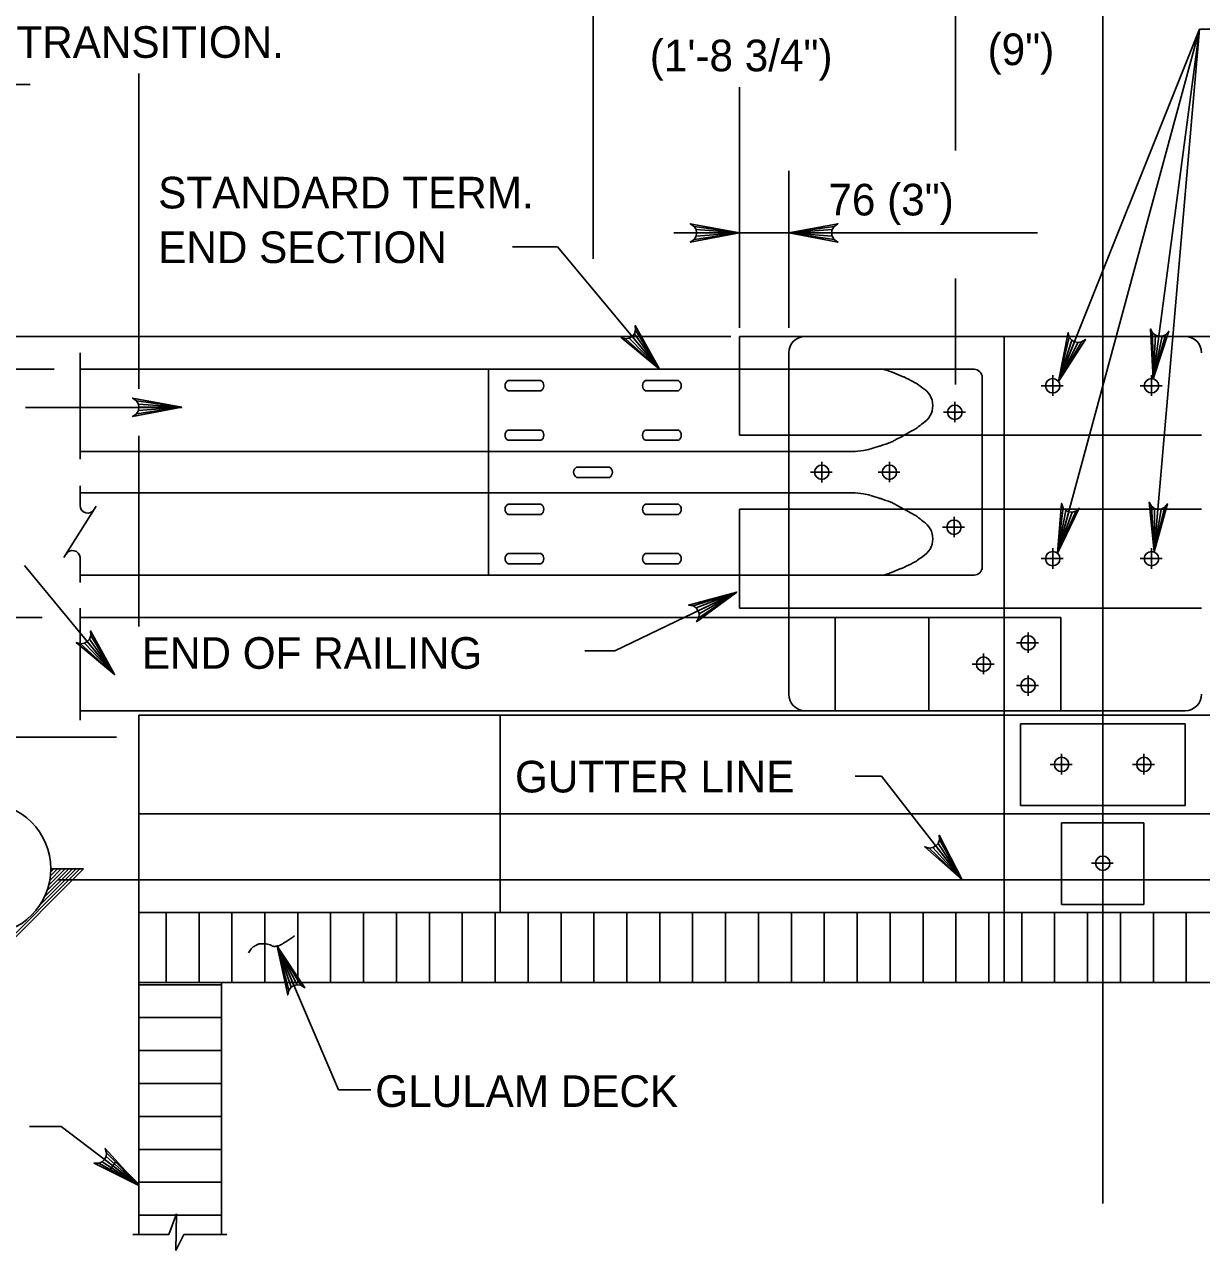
# Model space of a CAD drawing. Extents: x 0 to 36.3, y -66 to 0.
# Drawn here: x 4.419 to 8.89, y -16.519 to -11.865 of the extents above; entities that cross this region are included whole.
import ezdxf

# ---------------------------------------------------------------- set-up
doc = ezdxf.new("R2010")
doc.units = 0
for name, color, linetype in [('2', 7, 'Continuous'), ('3', 7, 'Continuous'), ('63', 7, 'Continuous')]:
    doc.layers.add(name, color=color, linetype=linetype)

# ---------------------------------------------------------------- blocks, each defined once
blk = doc.blocks.new('$X5430')
at = {"layer": '63'}
for p, q in [((5.4191, 3.4375), (5.6806, 3.4375)), ((5.4191, 3.3333), (5.6806, 3.3333)), ((5.4191, 3.2292), (5.6806, 3.2292)), ((5.4191, 3.125), (5.6806, 3.125)), ((5.4191, 3.0208), (5.6806, 3.0208)), ((5.4191, 2.9167), (5.6806, 2.9167)), ((5.4191, 2.8125), (5.6806, 2.8125)), ((5.4191, 2.7083), (5.6806, 2.7083))]:
    blk.add_line(p, q, dxfattribs=at)

msp = doc.modelspace()

# ---------------------------------------------------------------- linework, layer by layer
at = {"layer": '2'}
for p, q in [((7.1347, -13.0486), (9.1816, -13.0486)), ((8.1398, -13.0486), (8.1398, -15.5017)), ((4.6303, -13.1114), (4.6303, -13.5143)), ((7.3222, -13.1111), (7.3222, -13.9547)), ((4.6303, -13.1736), (6.1822, -13.1736)), ((6.1822, -13.1736), (6.1822, -13.9547)), ((6.1822, -13.1736), (8.0259, -13.1736)), ((6.2557, -13.2165), (6.3807, -13.2165)), ((6.7779, -13.2165), (6.9029, -13.2165)), ((7.1347, -13.1736), (7.1347, -13.4236)), ((8.0572, -13.2048), (8.0572, -13.9236)), ((8.3248, -13.1963), (8.3248, -13.2744)), ((8.6999, -13.1963), (8.6999, -13.2744)), ((6.2557, -13.2556), (6.3807, -13.2556)), ((6.7779, -13.2556), (6.9029, -13.2556)), ((8.2814, -13.2361), (8.3647, -13.2361)), ((8.6566, -13.2361), (8.7398, -13.2361)), ((7.953, -13.2968), (7.953, -13.3748)), ((7.9096, -13.3367), (7.9929, -13.3367)), ((6.2557, -13.404), (6.3807, -13.404)), ((6.2557, -13.4431), (6.3807, -13.4431)), ((6.7779, -13.404), (6.9029, -13.404)), ((6.7779, -13.4431), (6.9029, -13.4431)), ((7.1347, -13.4236), (8.8898, -13.4236)), ((4.6303, -13.4861), (7.5638, -13.4861)), ((7.4477, -13.5252), (7.4477, -13.6032)), ((7.7047, -13.5243), (7.7047, -13.6023)), ((6.5163, -13.5447), (6.6413, -13.5447)), ((6.5163, -13.5837), (6.6413, -13.5837)), ((7.4042, -13.5642), (7.4876, -13.5642)), ((7.6612, -13.5642), (7.7445, -13.5642)), ((4.6303, -13.6165), (4.6303, -13.6911)), ((4.6303, -13.6422), (7.5638, -13.6422)), ((4.6917, -13.6925), (4.5689, -13.8881)), ((6.2557, -13.6852), (6.3807, -13.6852)), ((6.2557, -13.7243), (6.3807, -13.7243)), ((6.7779, -13.6852), (6.9029, -13.6852)), ((6.7779, -13.7243), (6.9029, -13.7243)), ((7.1347, -13.7047), (8.8898, -13.7047)), ((7.1347, -13.7047), (7.1347, -13.9547)), ((7.9064, -13.7729), (7.9897, -13.7729)), ((7.9498, -13.7331), (7.9498, -13.8111)), ((8.3248, -13.8524), (8.3248, -13.9304)), ((8.6999, -13.8524), (8.6999, -13.9304)), ((4.6303, -13.8878), (4.6303, -13.9834)), ((6.2557, -13.8727), (6.3807, -13.8727)), ((6.2557, -13.9118), (6.3807, -13.9118)), ((6.7779, -13.8727), (6.9029, -13.8727)), ((6.7779, -13.9118), (6.9029, -13.9118)), ((8.2814, -13.8922), (8.3647, -13.8922)), ((8.6566, -13.8922), (8.7398, -13.8922)), ((4.6303, -13.9547), (8.0259, -13.9547)), ((7.3222, -13.9547), (7.3222, -14.4072)), ((7.1247, -14.0192), (6.6618, -14.2425)), ((4.6303, -14.0797), (4.6303, -14.506)), ((7.1347, -14.0797), (7.3222, -14.0797)), ((7.3222, -14.0797), (8.8898, -14.0797)), ((4.6303, -14.116), (8.3558, -14.116)), ((8.2311, -14.1723), (8.2311, -14.2503)), ((8.1877, -14.2122), (8.2709, -14.2122)), ((6.6618, -14.2425), (6.5474, -14.2425)), ((8.0619, -14.253), (8.0619, -14.331)), ((8.0185, -14.2928), (8.1018, -14.2928)), ((8.1877, -14.3736), (8.2709, -14.3736)), ((8.2311, -14.4134), (8.2311, -14.3354)), ((4.6303, -14.4697), (8.8273, -14.4697)), ((8.1398, -14.4697), (8.1398, -14.4861)), ((4.8531, -14.4861), (10.6802, -14.4861)), ((4.8531, -14.4861), (4.8531, -14.861)), ((6.2262, -14.4861), (6.2262, -15.236)), ((8.2023, -14.5197), (8.2023, -14.8297)), ((8.2023, -14.5197), (8.8273, -14.5197)), ((8.8273, -14.5197), (8.8273, -14.8297)), ((8.3586, -14.6337), (8.3586, -14.7117)), ((8.6711, -14.6337), (8.6711, -14.7117)), ((8.3152, -14.6735), (8.3985, -14.6735)), ((8.6277, -14.6735), (8.711, -14.6735)), ((8.2023, -14.8297), (8.8273, -14.8297)), ((4.8531, -14.861), (10.6802, -14.861)), ((8.3586, -14.8947), (8.3586, -15.2047)), ((8.3586, -14.8947), (8.6711, -14.8947)), ((8.6711, -14.8947), (8.6711, -15.2047)), ((8.5148, -15.0087), (8.5148, -15.0867)), ((8.4714, -15.0485), (8.5548, -15.0485)), ((8.3586, -15.2047), (8.6711, -15.2047)), ((4.8531, -15.236), (10.6802, -15.236)), ((4.8531, -15.5017), (10.6802, -15.5017)), ((4.8531, -15.5017), (4.8531, -16.4573)), ((5.1669, -15.5017), (5.1669, -16.4573)), ((4.5583, -16.0474), (4.4383, -16.0474)), ((4.8531, -16.2717), (4.5583, -16.0474))]:
    msp.add_line(p, q, dxfattribs=at)
msp.add_lwpolyline([(4.7667, -16.1808), (4.7436, -16.2135), (4.8531, -16.2665)], close=True, dxfattribs=at)
for centre in [(8.3248, -13.2361), (8.6999, -13.2361), (7.9529, -13.3367), (7.4476, -13.5642), (7.7046, -13.5642), (7.9498, -13.773), (8.3248, -13.8923), (8.6999, -13.8923), (8.231, -14.2122), (8.0619, -14.2929), (8.231, -14.3736), (8.3585, -14.6736), (8.671, -14.6736), (8.5148, -15.0486)]:
    msp.add_circle(centre, 0.0273, dxfattribs=at)
for centre, radius, start, end in [((7.3846, -13.1111), 0.0625, 90, 180), ((6.2674, -13.2361), 0.0228, 120.8559, 239.1441), ((6.369, -13.2361), 0.0228, 300.8559, 59.1441), ((6.7895, -13.2361), 0.0228, 120.8559, 239.1441), ((6.8912, -13.2361), 0.0228, 300.8559, 59.1441), ((7.4305, -13.9961), 0.8602, 71.5066, 72.9766), ((7.6528, -13.3314), 0.1594, 68.0907, 71.5066), ((5.6696, -18.2624), 5.4742, 67.6851, 68.0907), ((7.5577, -13.6622), 0.5016, 66.3453, 67.6851), ((7.677, -13.3899), 0.2044, 63.4251, 66.3453), ((6.5651, -15.6128), 2.6898, 62.6202, 63.4251), ((8.0259, -13.2048), 0.0312, 0, 90), ((7.7649, -13.2961), 0.0808, 54.6771, 62.6202), ((7.5957, -13.5349), 0.3735, 50.9849, 54.6771), ((7.7917, -13.3115), 0.0775, 301.3851, 59.6468), ((-8.0674, 15.7881), 33.224, 298.47252, 298.525), ((7.7546, -13.322), 0.092, 298.525, 306.8818), ((7.559, -13.0613), 0.4179, 306.8818, 310.7993), ((6.2674, -13.4236), 0.0228, 120.8559, 239.1441), ((6.369, -13.4236), 0.0228, 300.8559, 59.1441), ((6.7895, -13.4236), 0.0228, 120.8559, 239.1441), ((6.8912, -13.4236), 0.0228, 300.8559, 59.1441), ((7.6912, -13.3991), 0.0545, 290.2329, 298.3215), ((6.8564, -11.85), 1.8143, 298.3215, 298.7501), ((12.4105, -21.9738), 9.733, 118.56505, 118.75012), ((12.8667, -22.8118), 10.6871, 118.47252, 118.56505), ((7.5442, -13.061), 0.4255, 272.6429, 278.367), ((7.5795, -13.3014), 0.1825, 278.367, 287.1115), ((5.3449, -6.0426), 7.7775, 287.11147, 287.36106), ((7.5863, -13.2121), 0.2658, 287.3611, 288.7111), ((7.1784, -12.0079), 1.5372, 288.7111, 290.2329), ((6.5279, -13.5642), 0.0228, 120.8559, 239.1441), ((6.6296, -13.5642), 0.0228, 300.8559, 59.1441), ((7.5442, -14.0674), 0.4255, 81.633, 87.3571), ((7.5795, -13.827), 0.1825, 72.8885, 81.633), ((5.3449, -21.0858), 7.7775, 72.63894, 72.88853), ((7.5863, -13.9163), 0.2658, 71.2889, 72.6389), ((7.1784, -15.1205), 1.5372, 69.7671, 71.2889), ((7.6912, -13.7293), 0.0545, 61.6785, 69.7671), ((6.8564, -15.2784), 1.8143, 61.2499, 61.6785), ((4.6592, -13.6903), 0.0289, 180, 330), ((6.2674, -13.7048), 0.0228, 120.8559, 239.1441), ((6.369, -13.7048), 0.0228, 300.8559, 59.1441), ((6.7895, -13.7048), 0.0228, 120.8559, 239.1441), ((6.8912, -13.7048), 0.0228, 300.8559, 59.1441), ((12.4105, -5.1546), 9.733, 241.24988, 241.43495), ((12.8667, -4.3166), 10.6871, 241.43495, 241.52748), ((-8.0674, -42.9165), 33.224, 61.475, 61.52748), ((7.7546, -13.8064), 0.092, 53.1182, 61.475), ((7.559, -14.0671), 0.4179, 49.2007, 53.1182), ((7.7917, -13.8169), 0.0775, 300.3532, 58.6149), ((4.6015, -13.8904), 0.0289, 5.3286, 147.8672), ((6.2674, -13.8923), 0.0228, 120.8559, 239.1441), ((6.369, -13.8923), 0.0228, 300.8559, 59.1441), ((6.7895, -13.8923), 0.0228, 120.8559, 239.1441), ((6.8912, -13.8923), 0.0228, 300.8559, 59.1441), ((6.5651, -11.5156), 2.6898, 296.5749, 297.3798), ((7.7649, -13.8323), 0.0808, 297.3798, 305.3229), ((7.5957, -13.5935), 0.3735, 305.3229, 309.0151), ((7.4305, -13.1323), 0.8602, 287.0234, 288.4934), ((7.6528, -13.797), 0.1594, 288.4934, 291.9093), ((5.6696, -8.8659), 5.4742, 291.9093, 292.3149), ((7.5577, -13.4662), 0.5016, 292.3149, 293.6547), ((7.677, -13.7384), 0.2044, 293.6547, 296.5749), ((8.0259, -13.9236), 0.0312, 270, 0), ((7.3846, -14.4073), 0.0625, 180, 270), ((8.8273, -14.4073), 0.0625, 270, 0)]:
    msp.add_arc(centre, radius, start, end, dxfattribs=at)
at = {"layer": '3'}
for p, q in [((8.5148, -9.9667), (8.5148, -16.3403)), ((6.5788, -12.7536), (6.5788, -11.6451)), ((7.955, -11.7564), (7.955, -12.3434)), ((8.3432, -13.872), (8.8816, -11.8824)), ((8.3472, -13.2203), (8.8816, -11.8824)), ((8.7062, -13.2094), (8.8816, -11.8824)), ((8.7101, -13.8669), (8.8816, -11.8824)), ((8.8816, -11.8824), (9.0016, -11.8824)), ((4.853, -13.2478), (4.853, -12.0503)), ((4.4409, -12.092), (3.9409, -12.092)), ((7.1346, -12.7394), (7.1346, -12.1021)), ((7.3222, -12.4202), (7.3222, -13.016)), ((7.1347, -12.584), (7.1347, -13.016)), ((7.1178, -12.6559), (6.8853, -12.6559)), ((7.0464, -12.6559), (8.2669, -12.6559)), ((6.4442, -12.7081), (6.273, -12.7081)), ((6.8314, -13.1736), (6.4442, -12.7081)), ((7.955, -12.8288), (7.955, -13.2318)), ((7.1016, -13.0486), (2.1376, -13.0486)), ((7.1347, -13.0486), (7.1347, -13.1736)), ((4.5325, -13.1736), (2.8647, -13.1736)), ((4.4231, -13.318), (5.0162, -13.318)), ((4.853, -14.1495), (4.853, -13.4265)), ((4.7611, -14.3327), (4.4192, -13.9182)), ((7.1347, -13.9547), (7.1347, -14.0797)), ((4.4868, -14.116), (3.3232, -14.116)), ((7.4978, -14.4697), (7.4978, -14.116)), ((7.8545, -14.4697), (7.8545, -14.116)), ((8.3558, -14.4697), (8.3558, -14.116)), ((4.7689, -14.5695), (4.2689, -14.5695)), ((7.6739, -14.7177), (7.5749, -14.7177)), ((7.9812, -15.111), (7.6739, -14.7177)), ((4.8531, -14.861), (4.8531, -15.236)), ((4.2618, -15.4374), (4.6297, -15.0695)), ((4.2689, -15.4445), (4.6439, -15.0695)), ((4.4769, -15.2082), (4.6157, -15.0695)), ((4.4952, -15.1758), (4.6015, -15.0695)), ((4.5049, -15.1519), (4.5873, -15.0695)), ((4.5111, -15.1317), (4.5732, -15.0695)), ((4.515, -15.1136), (4.5591, -15.0695)), ((4.5174, -15.097), (4.5449, -15.0695)), ((4.5187, -15.0817), (4.5308, -15.0695)), ((4.6439, -15.0695), (4.5189, -15.0695)), ((9.7442, -15.111), (4.5488, -15.111)), ((4.8531, -15.236), (4.8531, -15.5017)), ((4.9571, -15.5017), (4.9571, -15.236)), ((5.0821, -15.5017), (5.0821, -15.236)), ((5.2071, -15.5017), (5.2071, -15.236)), ((5.3321, -15.5017), (5.3321, -15.236)), ((5.4571, -15.5017), (5.4571, -15.236)), ((5.5821, -15.5017), (5.5821, -15.236)), ((5.7071, -15.5017), (5.7071, -15.236)), ((5.8321, -15.5017), (5.8321, -15.236)), ((5.9571, -15.5017), (5.9571, -15.236)), ((6.0821, -15.5017), (6.0821, -15.236)), ((6.2071, -15.5017), (6.2071, -15.236)), ((6.3321, -15.5017), (6.3321, -15.236)), ((6.4571, -15.5017), (6.4571, -15.236)), ((6.5821, -15.5017), (6.5821, -15.236)), ((6.7071, -15.5017), (6.7071, -15.236)), ((6.8321, -15.5017), (6.8321, -15.236)), ((6.9571, -15.5017), (6.9571, -15.236)), ((7.0821, -15.5017), (7.0821, -15.236)), ((7.2071, -15.5017), (7.2071, -15.236)), ((7.3321, -15.5017), (7.3321, -15.236)), ((7.4571, -15.5017), (7.4571, -15.236)), ((7.5821, -15.5017), (7.5821, -15.236)), ((7.7071, -15.5017), (7.7071, -15.236)), ((7.8321, -15.5017), (7.8321, -15.236)), ((7.9571, -15.5017), (7.9571, -15.236)), ((8.0821, -15.5017), (8.0821, -15.236)), ((8.2071, -15.5017), (8.2071, -15.236)), ((8.3321, -15.5017), (8.3321, -15.236)), ((8.4571, -15.5017), (8.4571, -15.236)), ((8.5821, -15.5017), (8.5821, -15.236)), ((8.7071, -15.5017), (8.7071, -15.236)), ((8.8321, -15.5017), (8.8321, -15.236)), ((5.3784, -15.3632), (5.6113, -15.9092)), ((5.6113, -15.9092), (5.7351, -15.9092)), ((4.9676, -16.4573), (4.996, -16.3792)), ((4.996, -16.3792), (4.9937, -16.5186)), ((4.8312, -16.4573), (4.9676, -16.4573)), ((4.9937, -16.5186), (5.0244, -16.4573)), ((5.0244, -16.4573), (5.1872, -16.4573))]:
    msp.add_line(p, q, dxfattribs=at)
for points in [[(7.1347, -12.6559), (6.9482, -12.6908), (6.9626, -12.6809), (6.97, -12.6684), (6.9722, -12.6559), (6.97, -12.6434), (6.9626, -12.6309), (6.9482, -12.621), (7.1347, -12.6559), (6.9626, -12.6309), (6.97, -12.6434), (7.1347, -12.6559), (6.9722, -12.6559), (6.97, -12.6684), (7.1347, -12.6559), (6.9626, -12.6809)], [(7.3222, -12.6559), (7.5086, -12.621), (7.4943, -12.6309), (7.4868, -12.6434), (7.4847, -12.6559), (7.4868, -12.6684), (7.4943, -12.6809), (7.5086, -12.6908), (7.3222, -12.6559), (7.4943, -12.6809), (7.4868, -12.6684), (7.3222, -12.6559), (7.4847, -12.6559), (7.4868, -12.6434), (7.3222, -12.6559), (7.4943, -12.6309)], [(6.8314, -13.1736), (6.6853, -13.0527), (6.7022, -13.0573), (6.7165, -13.055), (6.7275, -13.0487), (6.7357, -13.039), (6.7406, -13.0253), (6.7391, -13.0079), (6.8314, -13.1736), (6.7406, -13.0253), (6.7357, -13.039), (6.8314, -13.1736), (6.7275, -13.0487), (6.7165, -13.055), (6.8314, -13.1736), (6.7022, -13.0573)], [(8.7062, -13.2094), (8.6959, -13.02), (8.7039, -13.0356), (8.7153, -13.0446), (8.7275, -13.0483), (8.7402, -13.0478), (8.7535, -13.0422), (8.7652, -13.0292), (8.7062, -13.2094), (8.7535, -13.0422), (8.7402, -13.0478), (8.7062, -13.2094), (8.7275, -13.0483), (8.7153, -13.0446), (8.7062, -13.2094), (8.7039, -13.0356)], [(8.3472, -13.2203), (8.3838, -13.0343), (8.3878, -13.0512), (8.3967, -13.0628), (8.4074, -13.0694), (8.4198, -13.0721), (8.4342, -13.0698), (8.4488, -13.0602), (8.3472, -13.2203), (8.4342, -13.0698), (8.4198, -13.0721), (8.3472, -13.2203), (8.4074, -13.0694), (8.3967, -13.0628), (8.3472, -13.2203), (8.3878, -13.0512)], [(5.0162, -13.3179), (4.8298, -13.3529), (4.8442, -13.3429), (4.8517, -13.3304), (4.8537, -13.3179), (4.8517, -13.3054), (4.8442, -13.2929), (4.8298, -13.283), (5.0162, -13.3179), (4.8442, -13.2929), (4.8517, -13.3054), (5.0162, -13.3179), (4.8537, -13.3179), (4.8517, -13.3304), (5.0162, -13.3179), (4.8442, -13.3429)], [(8.7101, -13.8669), (8.6913, -13.6782), (8.7, -13.6933), (8.7118, -13.7018), (8.7241, -13.705), (8.7367, -13.704), (8.7498, -13.6977), (8.7609, -13.6842), (8.7101, -13.8669), (8.7498, -13.6977), (8.7367, -13.704), (8.7101, -13.8669), (8.7241, -13.705), (8.7118, -13.7018), (8.7101, -13.8669), (8.7, -13.6933)], [(8.3432, -13.872), (8.3581, -13.6829), (8.364, -13.6994), (8.3741, -13.7098), (8.3856, -13.7152), (8.3982, -13.7163), (8.4123, -13.7124), (8.4256, -13.7012), (8.3432, -13.872), (8.4123, -13.7124), (8.3982, -13.7163), (8.3432, -13.872), (8.3856, -13.7152), (8.3741, -13.7098), (8.3432, -13.872), (8.364, -13.6994)], [(7.1247, -14.0192), (6.9719, -14.1318), (6.9806, -14.1165), (6.9818, -14.102), (6.9783, -14.0898), (6.9709, -14.0795), (6.9588, -14.0715), (6.9416, -14.0687), (7.1247, -14.0192), (6.9588, -14.0715), (6.9709, -14.0795), (7.1247, -14.0192), (6.9783, -14.0898), (6.9818, -14.102), (7.1247, -14.0192), (6.9806, -14.1165)], [(4.7612, -14.3327), (4.6156, -14.2111), (4.6324, -14.2158), (4.6467, -14.2137), (4.6578, -14.2073), (4.666, -14.1977), (4.671, -14.1841), (4.6695, -14.1667), (4.7612, -14.3327), (4.671, -14.1841), (4.666, -14.1977), (4.7612, -14.3327), (4.6578, -14.2073), (4.6467, -14.2137), (4.7612, -14.3327), (4.6324, -14.2158)], [(7.9812, -15.111), (7.8388, -14.9857), (7.8555, -14.9908), (7.8699, -14.989), (7.8811, -14.9829), (7.8897, -14.9736), (7.8949, -14.96), (7.8939, -14.9426), (7.9812, -15.111), (7.8949, -14.96), (7.8897, -14.9736), (7.9812, -15.111), (7.8811, -14.9829), (7.8699, -14.989), (7.9812, -15.111), (7.8555, -14.9908)], [(5.3784, -15.3632), (5.4837, -15.521), (5.4689, -15.5117), (5.4545, -15.5098), (5.4422, -15.5127), (5.4315, -15.5196), (5.4229, -15.5313), (5.4194, -15.5484), (5.3784, -15.3632), (5.4229, -15.5313), (5.4315, -15.5196), (5.3784, -15.3632), (5.4422, -15.5127), (5.4545, -15.5098), (5.3784, -15.3632), (5.4689, -15.5117)], [(4.8531, -16.2717), (4.6836, -16.1867), (4.701, -16.1874), (4.7145, -16.1819), (4.7237, -16.1732), (4.7296, -16.1621), (4.7313, -16.1476), (4.7258, -16.131), (4.8531, -16.2717), (4.7313, -16.1476), (4.7296, -16.1621), (4.8531, -16.2717), (4.7237, -16.1732), (4.7145, -16.1819), (4.8531, -16.2717), (4.701, -16.1874)]]:
    msp.add_lwpolyline(points, dxfattribs=at)
msp.add_circle((4.2689, -15.0695), 0.25, dxfattribs=at)
for centre, radius, start, end in [((8.8273, -13.1111), 0.0625, 0, 90), ((5.3854, -15.5182), 0.1803, 116.5624, 121.4049), ((5.3148, -15.377), 0.0224, 102.8072, 116.5624), ((5.3185, -15.3934), 0.0393, 90, 102.8072), ((5.3185, -15.5371), 0.183, 84.0775, 90), ((5.332, -15.4069), 0.0521, 61.2712, 84.0775), ((5.3609, -15.2915), 0.074, 288.433, 300.6618), ((5.178, -14.9829), 0.4328, 300.6618, 302.0024), ((4.618, -14.0868), 1.4894, 302.0024, 302.725), ((5.3142, -15.1702), 0.2016, 302.725, 305.5345), ((5.1055, -14.8781), 0.5606, 305.5345, 307.2191), ((5.3385, -15.4245), 0.0773, 138.8108, 152.4815), ((5.3163, -15.4051), 0.0478, 121.4049, 138.8108), ((5.3692, -15.339), 0.0254, 241.2712, 274.1568), ((5.3671, -15.3101), 0.0544, 274.1568, 288.433)]:
    msp.add_arc(centre, radius, start, end, dxfattribs=at)

# ---------------------------------------------------------------- block references
at = {"layer": '2', "xscale": 1.1999976, "yscale": 1.1999976}
msp.add_blockref('$X5430', (-1.6498, -19.6347), dxfattribs=at)

# ---------------------------------------------------------------- texts
at = {"layer": '3'}
for s, p in [('   GUIDE RAIL TRANSITION.', (3.3006, -11.9912)), ('(9")', (8.0774, -12.0188)), ('(1\'-8 3/4")', (6.7943, -12.0422)), ('STANDARD TERM.', (4.9269, -12.5629)), ('76 (3")', (7.4727, -12.5895)), ('END SECTION', (4.9269, -12.7702)), ('END OF RAILING', (4.8648, -14.3104)), ('GUTTER LINE', (6.2823, -14.7798)), ('GLULAM DECK', (5.7516, -15.9736))]:
    msp.add_text(s, height=0.12, dxfattribs=at).set_placement(p)

doc.saveas('drawing.dxf')
